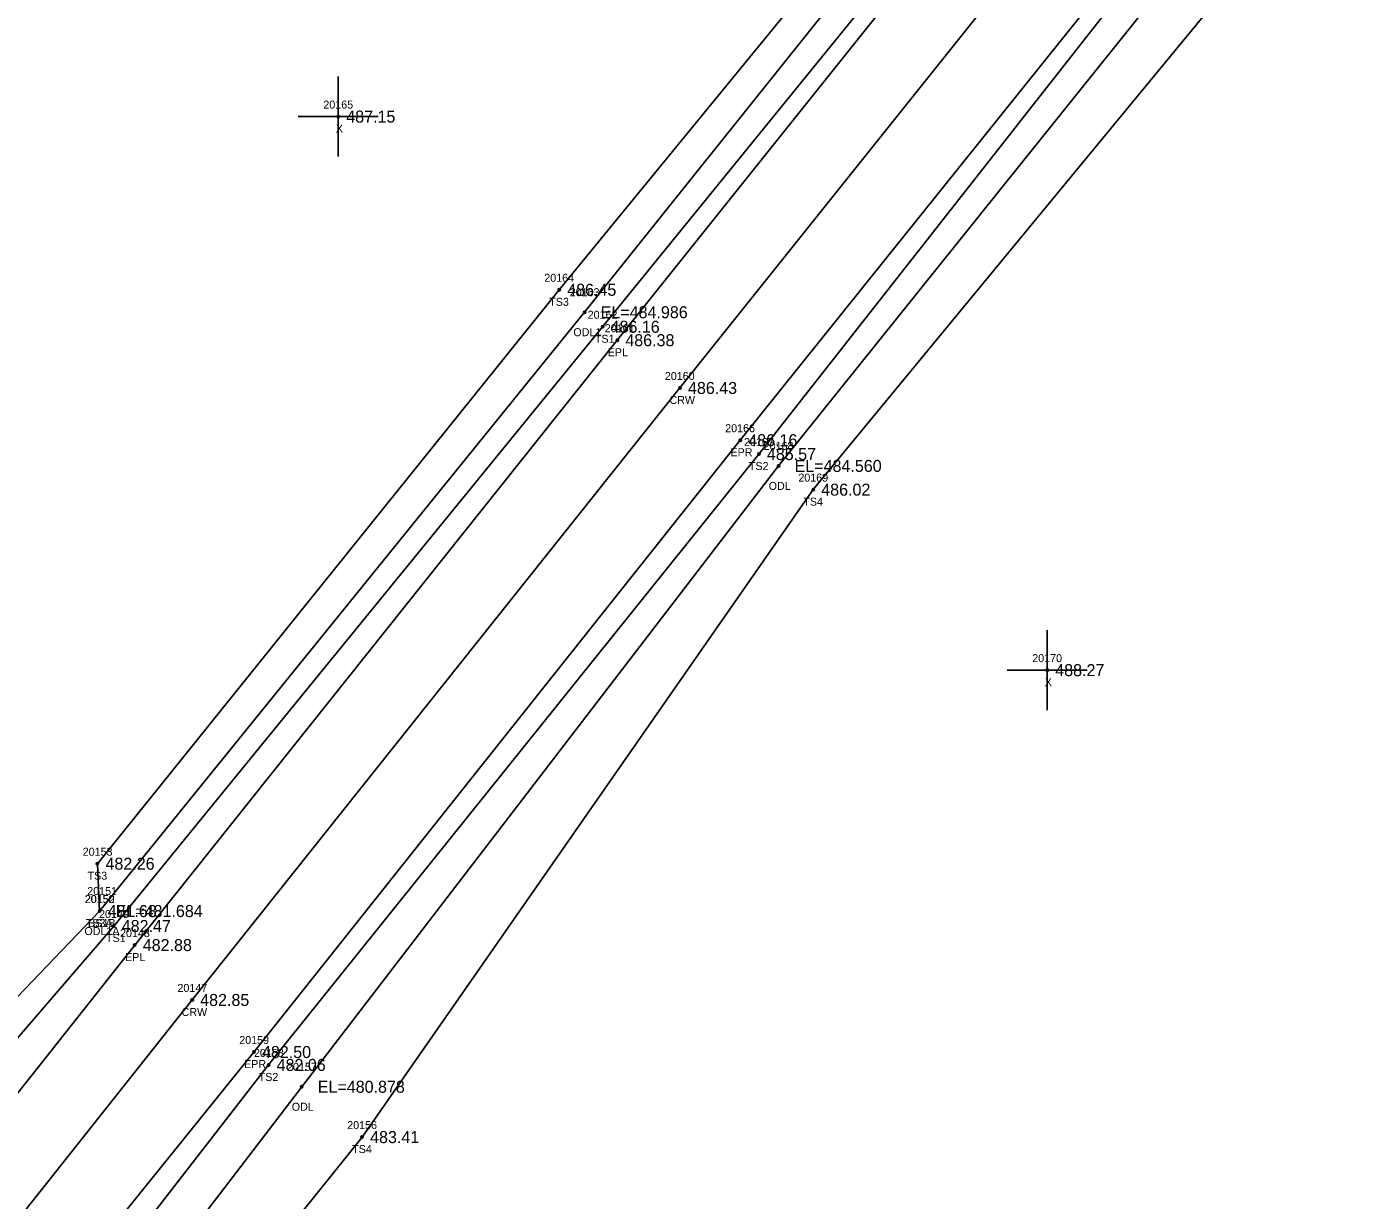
# Model space of a CAD drawing. Extents: x 1789565 to 1790548, y 909019 to 910194.
# Drawn here: x 1790172.5 to 1790338.1, y 909753.6 to 909900.3 of the extents above; entities that cross this region are included whole.
import ezdxf

# ---------------------------------------------------------------- set-up
doc = ezdxf.new("R2010")
doc.units = 0
for name, color, linetype in [('RD_DTM_BkLn1', 7, 'Continuous'), ('RD_DTM_BkLn2', 7, 'Continuous'), ('RD_DTM_BkLn_txCode', 7, 'Continuous'), ('RD_EX_H2O', 7, 'Continuous'), ('RD_EX_H2O_txCode', 7, 'Continuous'), ('RD_EX_Misc', 7, 'Continuous'), ('RD_EX_Misc_txCode', 7, 'Continuous'), ('RD_EX_Road', 7, 'Continuous'), ('RD_EX_Road_txCode', 7, 'Continuous'), ('RD_EX_TX_H2O_ELEV', 7, 'Continuous'), ('RD_EX_TX_Misc_ELEV', 7, 'Continuous'), ('RD_EX_TX_Road_ELEV', 7, 'Continuous'), ('RD_HC_Survey_ELEV', 7, 'Continuous'), ('RD_HC_Survey_txCode', 7, 'Continuous'), ('RD_SMD_Locator', 7, 'Continuous')]:
    doc.layers.add(name, color=color, linetype=linetype)

msp = doc.modelspace()

# ---------------------------------------------------------------- linework, layer by layer
at = {"layer": 'RD_DTM_BkLn1'}
msp.add_lwpolyline([(1790071.24, 909625.67), (1790132.78, 909702.56), (1790193.17, 909778.64), (1790254.11, 909855.13), (1790314.56, 909930.82), (1790375.87, 910006.79), (1790434.17, 910078.51), (1790495.95, 910153.23)], dxfattribs=at)
at = {"layer": 'RD_DTM_BkLn2'}
for points in [[(1790181.61, 909789.75), (1790181.34, 909795.67), (1790239.02, 909867.4), (1790301.11, 909943.25), (1790360.06, 910019.74), (1790418.43, 910091.45), (1790480.61, 910166.7)], [(1790060.69, 909634.71), (1790061.47, 909641.75), (1790119.6, 909713.74), (1790183.37, 909787.88), (1790244.44, 909862.78), (1790306.19, 909938.82), (1790365.07, 910016.23), (1790422.97, 910088.22), (1790484.03, 910163.43)], [(1790081.67, 909617.32), (1790086.3, 909617), (1790143.13, 909693.7), (1790202.72, 909770.52), (1790263.97, 909846.87), (1790323.52, 909922.76), (1790384.66, 909999.25), (1790423.96, 910046.28)], [(1790092.97, 909612.92), (1790097.34, 909612.95), (1790152.91, 909684.97), (1790214.4, 909761.5), (1790270.76, 909842.42), (1790331.58, 909916.3), (1790391.85, 909993.49), (1790427.85, 910042.91), (1790426.19, 910046.57), (1790423.96, 910046.28)], [(1790057.63, 909630.78), (1790055.38, 909644.82), (1790114.17, 909719.34), (1790181.61, 909789.75)]]:
    msp.add_lwpolyline(points, dxfattribs=at)
at = {"layer": 'RD_EX_H2O'}
for points in [[(1790181.61, 909789.75), (1790242.2, 909864.6), (1790303.39, 909941.16), (1790363.14, 910017.91), (1790421.33, 910089.83), (1790482.18, 910165.24)], [(1790092.97, 909612.92), (1790147.38, 909690.09), (1790206.86, 909767.79), (1790266.43, 909845.39), (1790326.38, 909920.19), (1790387.41, 909997.35), (1790424.69, 910044.32)]]:
    msp.add_lwpolyline(points, dxfattribs=at)
at = {"layer": 'RD_EX_Misc'}
for p, q in [((1790211.42, 909884.05), (1790211.42, 909894.05)), ((1790206.42, 909889.05), (1790216.42, 909889.05)), ((1790299.99, 909814.86), (1790299.99, 909824.86)), ((1790294.99, 909819.86), (1790304.99, 909819.86))]:
    msp.add_line(p, q, dxfattribs=at)
at = {"layer": 'RD_EX_Road'}
for points in [[(1790071.29, 909625.64), (1790063.58, 909631.76), (1790124.98, 909708.45), (1790186, 909785.5), (1790246.28, 909861.1), (1790307.38, 909937.59), (1790368.26, 910012.93), (1790426.56, 910084.73), (1790488.45, 910159.81)], [(1790071.25, 909625.72), (1790078.96, 909619.74), (1790139.76, 909696.36), (1790200.89, 909772.13), (1790261.64, 909848.6), (1790322.1, 909924.01), (1790383.38, 910000.26), (1790441.69, 910072.01), (1790503.77, 910147.05)]]:
    msp.add_lwpolyline(points, dxfattribs=at)
at = {"layer": 'RD_SMD_Locator'}
for centre in [(1790211.42, 909889.05), (1790239.02, 909867.4), (1790242.2, 909864.6), (1790244.44, 909862.78), (1790246.28, 909861.1), (1790254.11, 909855.13), (1790261.64, 909848.6), (1790263.97, 909846.87), (1790266.43, 909845.39), (1790270.76, 909842.42), (1790299.99, 909819.86), (1790181.34, 909795.67), (1790181.61, 909789.75), (1790181.61, 909789.75), (1790181.61, 909789.75), (1790183.37, 909787.88), (1790186, 909785.5), (1790193.17, 909778.64), (1790200.89, 909772.13), (1790202.72, 909770.52), (1790206.86, 909767.79), (1790214.4, 909761.5)]:
    msp.add_circle(centre, 0.15, dxfattribs=at)

# ---------------------------------------------------------------- texts
at = {"layer": 'RD_DTM_BkLn_txCode'}
for s, p in [('20164', (1790237.16, 909868.4)), ('TS3', (1790237.78, 909865.4)), ('20162', (1790242.58, 909863.78)), ('TS1', (1790243.48, 909860.78)), ('20167', (1790262.11, 909847.87)), ('TS2', (1790262.72, 909844.87)), ('20169', (1790268.9, 909843.42)), ('TS4', (1790269.52, 909840.42)), ('20153', (1790179.5, 909796.67)), ('TS3', (1790180.1, 909793.67)), ('20150', (1790179.74, 909790.75)), ('20152', (1790179.78, 909790.75)), ('20149', (1790181.54, 909788.88)), ('TS3A', (1790179.88, 909787.75)), ('BS1B', (1790180.19, 909787.75)), ('TS1', (1790182.41, 909785.88)), ('20158', (1790200.89, 909771.52)), ('TS2', (1790201.48, 909768.52)), ('20156', (1790212.54, 909762.5)), ('TS4', (1790213.16, 909759.5))]:
    msp.add_text(s, height=1, dxfattribs=at).set_placement(p)
at = {"layer": 'RD_EX_H2O_txCode'}
for s, p in [('20163', (1790240.34, 909866.6)), ('ODL1', (1790240.79, 909861.6)), ('20168', (1790264.57, 909847.39)), ('ODL', (1790265.19, 909842.39)), ('20151', (1790180.06, 909791.75)), ('ODL1A', (1790179.71, 909786.75)), ('20157', (1790205.02, 909769.79)), ('ODL', (1790205.61, 909764.79))]:
    msp.add_text(s, height=1, dxfattribs=at).set_placement(p)
at = {"layer": 'RD_EX_Misc_txCode'}
for s, p in [('20165', (1790209.56, 909890.05)), ('X', (1790211.11, 909887.05)), ('20170', (1790298.12, 909820.86)), ('X', (1790299.68, 909817.86))]:
    msp.add_text(s, height=1, dxfattribs=at).set_placement(p)
at = {"layer": 'RD_EX_Road_txCode'}
for s, p in [('20161', (1790244.71, 909862.1)), ('EPL', (1790245.08, 909859.1)), ('20166', (1790259.76, 909849.6)), ('EPR', (1790260.42, 909846.6)), ('20148', (1790184.16, 909786.5)), ('EPL', (1790184.79, 909783.5)), ('20159', (1790199.05, 909773.13)), ('EPR', (1790199.66, 909770.13))]:
    msp.add_text(s, height=1, dxfattribs=at).set_placement(p)
at = {"layer": 'RD_EX_TX_H2O_ELEV'}
for s, p in [('EL=484.986', (1790244.2, 909863.85)), ('EL=484.560', (1790268.43, 909844.64)), ('EL=481.684', (1790183.61, 909789)), ('EL=480.878', (1790208.86, 909767.04))]:
    msp.add_text(s, height=1.5, dxfattribs=at).set_placement(p)
at = {"layer": 'RD_EX_TX_Misc_ELEV'}
for s, p in [('487.15', (1790212.42, 909888.3)), ('486.45', (1790240.02, 909866.65)), ('486.16', (1790245.44, 909862.03)), ('485.57', (1790264.97, 909846.12)), ('486.02', (1790271.76, 909841.67)), ('488.27', (1790300.99, 909819.11)), ('482.26', (1790182.34, 909794.92)), ('481.68', (1790182.61, 909789)), ('481.68', (1790182.61, 909789)), ('482.47', (1790184.37, 909787.13)), ('482.06', (1790203.72, 909769.77)), ('483.41', (1790215.4, 909760.75))]:
    msp.add_text(s, height=1.5, dxfattribs=at).set_placement(p)
at = {"layer": 'RD_EX_TX_Road_ELEV'}
for s, p in [('486.38', (1790247.28, 909860.35)), ('486.16', (1790262.64, 909847.85)), ('482.88', (1790187, 909784.75)), ('482.50', (1790201.89, 909771.38))]:
    msp.add_text(s, height=1.5, dxfattribs=at).set_placement(p)
at = {"layer": 'RD_HC_Survey_ELEV'}
for s, p in [('486.43', (1790255.11, 909854.38)), ('482.85', (1790194.17, 909777.89))]:
    msp.add_text(s, height=1.5, dxfattribs=at).set_placement(p)
at = {"layer": 'RD_HC_Survey_txCode'}
for s, p in [('20160', (1790252.22, 909856.13)), ('CRW', (1790252.8, 909853.13)), ('20147', (1790191.33, 909779.64)), ('CRW', (1790191.85, 909776.64))]:
    msp.add_text(s, height=1, dxfattribs=at).set_placement(p)

doc.saveas('drawing.dxf')
